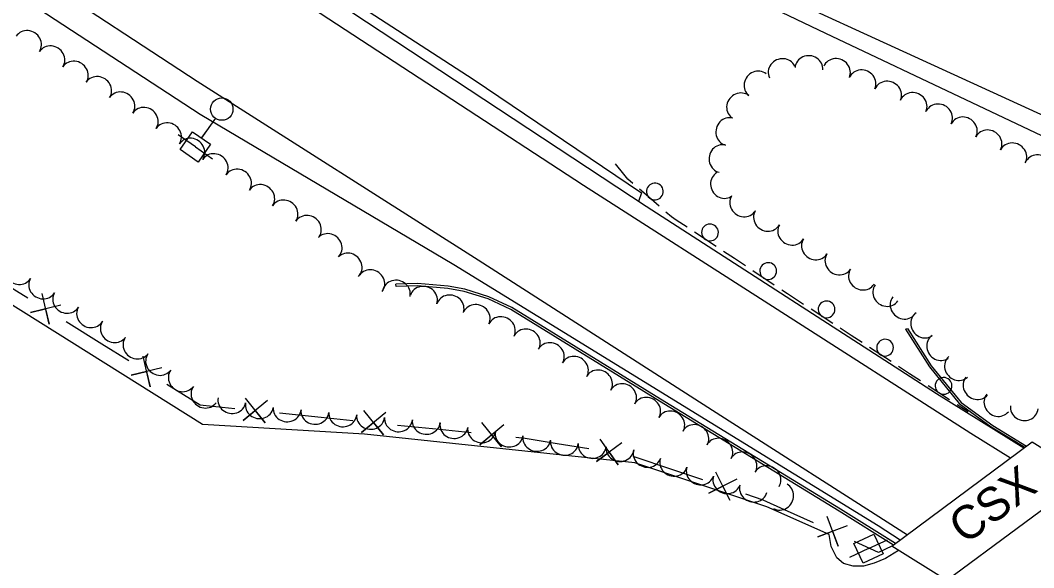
# Model space of a CAD drawing. Extents: x 1746010 to 1754829, y 655801 to 663091.
# Drawn here: x 1751496.6 to 1751859.2, y 659030.7 to 659226.6 of the extents above; entities that cross this region are included whole.
import ezdxf

# ---------------------------------------------------------------- set-up
doc = ezdxf.new("R2010")
doc.units = 0
for name, color, linetype in [('SURVEY - AERIAL SURVEY - Photo Control - Points - Elevations', 7, 'Continuous'), ('SURVEY - AERIAL SURVEY - Photo Control - Points - Locators', 7, 'Continuous'), ('SURVEY - AERIAL SURVEY - Photo Control - Points - Numbers', 7, 'Continuous'), ('SURVEY - CENTERLINE - Existing Roads - Development', 7, 'Continuous'), ('SURVEY - CENTERLINE - Existing Roads Curve Text', 7, 'Continuous'), ('SURVEY - CENTERLINE - Existing Roads Text', 7, 'Continuous'), ('SURVEY - CONTROL - Points - Numbers', 7, 'Continuous')]:
    doc.layers.add(name, color=color, linetype=linetype)

msp = doc.modelspace()

# ---------------------------------------------------------------- linework, layer by layer
at = {"layer": 'SURVEY - AERIAL SURVEY - Photo Control - Points - Elevations'}
for points in [[(1751136.82, 659554.52), (1751217.01, 659499.16), (1751310.15, 659435.49), (1751402.66, 659374.15), (1751479.7, 659322.87), (1751569.69, 659263.28), (1751658.69, 659205.51), (1751718.84, 659164.93), (1751717.79, 659161.8)], [(1751808.51, 659038.41), (1751858.64, 659075.74), (1751878.49, 659063.36), (1751828.11, 659026.2)], [(1751828.11, 659026.2), (1751808.51, 659038.41)]]:
    msp.add_lwpolyline(points, dxfattribs=at)
at = {"layer": 'SURVEY - AERIAL SURVEY - Photo Control - Points - Locators'}
for points in [[(1751850.89, 659069.97), (1751836.71, 659078.71), (1751698.09, 659167.45), (1751556.82, 659259.91), (1751409.51, 659356.6), (1751240.26, 659471.26), (1751108.21, 659560.28), (1750949.44, 659670.61), (1750790.01, 659782.16), (1750639.25, 659888.39), (1750537.27, 659960.87), (1750507.28, 659982.53)], [(1751811.46, 659040.6), (1751803.54, 659045.66), (1751651.7, 659139.14), (1751560.97, 659192.86), (1751430.95, 659277.83), (1751226.31, 659416.5), (1751044.68, 659538.71), (1750870.37, 659656.91), (1750693.9, 659781.14), (1750567.77, 659872.76), (1750445.81, 659959.59)], [(1750464.75, 659959.09), (1750533.91, 659909.95), (1750645.13, 659831.38), (1750753.4, 659754.5), (1750870.59, 659672.13), (1750959.5, 659609.93), (1751081.2, 659527.03), (1751199.52, 659445.74), (1751320.31, 659364.23), (1751443.12, 659281.31), (1751559.93, 659204.83), (1751660.4, 659140.92), (1751744.29, 659087.1), (1751814.04, 659042.53)], [(1751855.66, 659073.53), (1751824.49, 659092.89), (1751720.6, 659159.95), (1751578.18, 659253.97), (1751455.85, 659335.43), (1751347.45, 659406.77), (1751242.7, 659477.43), (1751134.7, 659551.49), (1751142.63, 659562.83), (1751231.24, 659513.59), (1751353.03, 659442.63), (1751480.52, 659374.44), (1751556.22, 659335.73), (1751679.55, 659272.32), (1751784.68, 659222.03), (1751889.47, 659172.35), (1751954.53, 659146.62)], [(1751692.52, 659270.52), (1751888.55, 659180.68), (1751962.99, 659152.25)], [(1751810.9, 659036.92), (1751806.26, 659034), (1751802.13, 659032.39), (1751798.35, 659031.28), (1751794.6, 659031.28), (1751791.12, 659032.21), (1751788.78, 659034.22), (1751786.74, 659038.28), (1751785.99, 659042.56), (1751763.7, 659052.53), (1751716.54, 659068.26), (1751619.81, 659078.53), (1751561.8, 659081.97), (1751438.68, 659159.11), (1751425.89, 659140.29), (1751454.93, 659067.9)]]:
    msp.add_lwpolyline(points, dxfattribs=at)
at = {"layer": 'SURVEY - AERIAL SURVEY - Photo Control - Points - Numbers'}
for points in [[(1751712.57, 659171.6), (1751709.62, 659175.27)], [(1751715.82, 659168.23), (1751714, 659169.82), (1751712.57, 659171.6)], [(1751725.18, 659160.1), (1751720.53, 659164.13), (1751718.23, 659166.13)], [(1751731.31, 659155.14), (1751729.64, 659156.25), (1751727.6, 659158.01)], [(1751735.23, 659152.54), (1751731.31, 659155.14)], [(1751745.56, 659145.69), (1751737.89, 659150.77)], [(1751752.14, 659141.32), (1751748.23, 659143.92)], [(1751756.06, 659138.72), (1751752.14, 659141.32)], [(1751766.39, 659131.86), (1751758.72, 659136.95)], [(1751809.8, 659039.37), (1751790.05, 659051.7), (1751727.21, 659090.04), (1751672.46, 659123.85), (1751664.28, 659127.7), (1751655.64, 659130.37), (1751649.7, 659131.53), (1751638.72, 659132.45), (1751631.04, 659132.2)], [(1751809.1, 659038.85), (1751789.64, 659051), (1751726.84, 659089.32), (1751672.17, 659123.08), (1751664.08, 659126.89), (1751655.5, 659129.54), (1751649.62, 659130.68), (1751638.71, 659131.59), (1751631.07, 659131.33), (1751631.04, 659132.2)], [(1751772.98, 659127.51), (1751771.15, 659128.71), (1751769.06, 659130.09)], [(1751776.92, 659124.94), (1751772.98, 659127.51)], [(1751787.3, 659118.16), (1751779.6, 659123.19)], [(1751793.91, 659113.83), (1751789.98, 659116.41)], [(1751813.33, 659116.08), (1751814.08, 659116.36), (1751822.6, 659102.91), (1751833.23, 659089.88), (1751844.58, 659081.57), (1751856.66, 659074.27)], [(1751813.33, 659116.08), (1751821.9, 659102.58), (1751832.6, 659089.46), (1751844.01, 659081.1), (1751856.04, 659073.81)], [(1751797.85, 659111.27), (1751793.91, 659113.83)], [(1751808.23, 659104.48), (1751800.53, 659109.52)], [(1751814.84, 659100.16), (1751810.91, 659102.73)], [(1751818.78, 659097.59), (1751814.84, 659100.16)], [(1751829.16, 659090.81), (1751821.46, 659095.84)], [(1751835.78, 659086.49), (1751831.84, 659089.06)]]:
    msp.add_lwpolyline(points, dxfattribs=at)
for centre, start, end in [((1751723.69, 659165.34), 342.3037, 342.2897), ((1751743.41, 659150.69), 349.5923, 349.5783), ((1751764.24, 659136.87), 349.5923, 349.5783), ((1751785.11, 659123.15), 350.0073, 349.9933), ((1751806.05, 659109.47), 350.0073, 349.9933), ((1751826.98, 659095.8), 350.0073, 349.9933)]:
    msp.add_arc(centre, 3, start, end, dxfattribs=at)
at = {"layer": 'SURVEY - CENTERLINE - Existing Roads - Development'}
for points in [[(1751499.32, 659127.17), (1751489.63, 659133.18)], [(1751511.17, 659124.65), (1751500.24, 659122.02), (1751505.66, 659123.36), (1751506.95, 659117.85), (1751504.46, 659128.81)], [(1751525.75, 659110.78), (1751513, 659118.69)], [(1751535.44, 659104.77), (1751525.75, 659110.78)], [(1751547.29, 659102.24), (1751536.35, 659099.61), (1751541.78, 659100.95), (1751543.07, 659095.45), (1751540.57, 659106.41)], [(1751562.01, 659088.8), (1751561.02, 659088.9), (1751549.12, 659096.28)], [(1751585.11, 659090.55), (1751576.43, 659083.4), (1751580.72, 659086.98), (1751584.29, 659082.59), (1751577.25, 659091.35)], [(1751573.35, 659087.63), (1751562.01, 659088.8)], [(1751604.29, 659084.46), (1751589.37, 659085.99)], [(1751627.39, 659086.22), (1751618.71, 659079.07), (1751623, 659082.65), (1751626.57, 659078.26), (1751619.53, 659087.02)], [(1751615.63, 659083.3), (1751604.29, 659084.46)], [(1751646.57, 659080.13), (1751631.65, 659081.66)], [(1751669.67, 659081.89), (1751661, 659074.73), (1751665.28, 659078.31), (1751668.85, 659073.93), (1751661.81, 659082.69)], [(1751657.91, 659078.97), (1751646.57, 659080.13)], [(1751688.75, 659075.08), (1751677.25, 659076.99), (1751673.93, 659077.33)], [(1751700, 659073.21), (1751688.75, 659075.08)], [(1751711.91, 659075.39), (1751702.81, 659068.79), (1751707.31, 659072.1), (1751710.6, 659067.5), (1751704.12, 659076.69)], [(1751730.1, 659065.8), (1751715.92, 659070.57), (1751715.88, 659070.58)], [(1751740.9, 659062.17), (1751730.1, 659065.8)], [(1751753.02, 659062.42), (1751742.98, 659057.36), (1751747.95, 659059.9), (1751750.47, 659054.84), (1751745.53, 659064.94)], [(1751770.06, 659051.45), (1751762.38, 659054.94), (1751756.17, 659057.04)], [(1751780.44, 659046.74), (1751770.06, 659051.45)], [(1751792.51, 659045.76), (1751782.02, 659041.74), (1751787.22, 659043.77), (1751789.21, 659038.48), (1751785.32, 659049.03)], [(1751808.51, 659038.41), (1751803.67, 659036.19), (1751795.09, 659040.08)]]:
    msp.add_lwpolyline(points, dxfattribs=at)
at = {"layer": 'SURVEY - CENTERLINE - Existing Roads Curve Text'}
for p, q in [((1751566.49, 659191.62), (1751561.5, 659184.5)), ((1751561.73, 659184.82), (1751563.56, 659187.45)), ((1751559.26, 659181.3), (1751553.12, 659185.6)), ((1751559.26, 659181.3), (1751565.41, 659177)), ((1751800.12, 659037.55), (1751806.9, 659040.75)), ((1751800.12, 659037.55), (1751793.33, 659034.34))]:
    msp.add_line(p, q, dxfattribs=at)
for points in [[(1751553.83, 659180.34), (1751558.3, 659186.73), (1751564.7, 659182.26), (1751560.22, 659175.87)], [(1751794.92, 659039.41), (1751801.98, 659042.74), (1751805.31, 659035.69), (1751798.26, 659032.36)]]:
    msp.add_lwpolyline(points, close=True, dxfattribs=at)
msp.add_circle((1751568.72, 659194.82), 4, dxfattribs=at)
at = {"layer": 'SURVEY - CENTERLINE - Existing Roads Text'}
for centre, major_axis in [((1751499.3, 659218.15), (4.18, -2.74)), ((1751507.66, 659212.67), (4.18, -2.74)), ((1751516.03, 659207.19), (4.18, -2.74)), ((1751769.19, 659208.14), (4.54, 2.09)), ((1751778.81, 659209.26), (4.98, -0.42)), ((1751788.7, 659208.15), (4.57, -2.03)), ((1751760.42, 659203.56), (3.12, 3.91)), ((1751797.84, 659204.1), (4.57, -2.03)), ((1751524.39, 659201.7), (4.17, -2.76)), ((1751806.98, 659200.04), (4.57, -2.03)), ((1751532.72, 659196.18), (4.17, -2.76)), ((1751754.18, 659195.74), (3.12, 3.91)), ((1751816.12, 659195.99), (4.57, -2.03)), ((1751541.06, 659190.65), (4.17, -2.76)), ((1751825.24, 659191.89), (4.43, -2.33)), ((1751549.4, 659185.13), (4.17, -2.76)), ((1751750.22, 659186.79), (1.31, 4.82)), ((1751834.1, 659187.24), (4.43, -2.33)), ((1751842.95, 659182.59), (4.43, -2.33)), ((1751557.74, 659179.61), (4.17, -2.76)), ((1751851.8, 659177.94), (4.43, -2.33)), ((1751566.07, 659174.08), (4.17, -2.76)), ((1751747.77, 659177.13), (1.08, 4.88)), ((1751860.81, 659173.69), (4.53, -2.11)), ((1751574.41, 659168.56), (4.17, -2.76)), ((1751748.38, 659167.82), (-2.53, 4.31)), ((1751582.75, 659163.04), (4.17, -2.76)), ((1751591.08, 659157.51), (4.17, -2.76)), ((1751755.39, 659161.1), (-4.24, 2.65)), ((1751763.92, 659155.91), (-4.33, 2.5)), ((1751599.42, 659151.99), (4.17, -2.76)), ((1751606.91, 659145.43), (3.58, -3.49)), ((1751772.56, 659150.94), (-4.33, 2.5)), ((1751781.06, 659145.7), (-4.21, 2.7)), ((1751614.07, 659138.45), (3.58, -3.49)), ((1751789.47, 659140.3), (-4.21, 2.7)), ((1751495.99, 659136.84), (-4.29, 2.57)), ((1751622.13, 659132.55), (4.03, -2.95)), ((1751797.89, 659134.89), (-4.21, 2.7)), ((1751504.57, 659131.7), (-4.29, 2.57)), ((1751631.19, 659128.87), (4.89, -1.05)), ((1751513.15, 659126.56), (-4.29, 2.57)), ((1751640.94, 659126.69), (4.75, -1.55)), ((1751650.44, 659123.59), (4.75, -1.55)), ((1751806.57, 659129.06), (-4.1, 2.87)), ((1751659.8, 659120.13), (4.5, -2.18)), ((1751812.77, 659124.52), (-3.92, 3.11)), ((1751521.72, 659121.42), (-4.29, 2.57)), ((1751820.06, 659117.84), (-2.89, 4.08)), ((1751530.16, 659116.07), (-4.06, 2.92)), ((1751668.8, 659115.79), (4.5, -2.18)), ((1751677.73, 659111.36), (4.35, -2.47)), ((1751538.27, 659110.22), (-4.06, 2.92)), ((1751686.34, 659106.47), (4.35, -2.47)), ((1751825.77, 659109.77), (-2.89, 4.08)), ((1751546.38, 659104.37), (-4.06, 2.92)), ((1751694.96, 659101.58), (4.35, -2.47)), ((1751832.18, 659102.6), (-3.35, 3.71)), ((1751554.5, 659098.52), (-4.06, 2.92)), ((1751703.57, 659096.69), (4.35, -2.47)), ((1751712.19, 659091.8), (4.35, -2.47)), ((1751838.87, 659095.74), (-3.88, 3.15)), ((1751562.61, 659092.67), (-4.06, 2.92)), ((1751846.32, 659089.7), (-3.88, 3.15)), ((1751572.34, 659090.62), (-4.92, 0.91)), ((1751582.17, 659088.8), (-4.92, 0.91)), ((1751720.8, 659086.91), (4.35, -2.47)), ((1751592.09, 659087.64), (-4.98, 0.45)), ((1751602.05, 659086.74), (-4.98, 0.45)), ((1751612.01, 659085.85), (-4.98, 0.45)), ((1751621.97, 659084.96), (-4.98, 0.45)), ((1751729.42, 659082.02), (4.35, -2.47)), ((1751855.87, 659088.11), (-4.97, 0.57)), ((1751631.93, 659084.07), (-4.98, 0.45)), ((1751641.89, 659083.17), (-4.98, 0.45)), ((1751651.78, 659081.67), (-4.94, 0.76)), ((1751738.03, 659077.14), (4.35, -2.47)), ((1751661.66, 659080.15), (-4.94, 0.76)), ((1751671.54, 659078.63), (-4.94, 0.76)), ((1751681.42, 659077.11), (-4.94, 0.76)), ((1751691.32, 659075.69), (-4.97, 0.56)), ((1751701.26, 659074.57), (-4.97, 0.56)), ((1751746.65, 659072.25), (4.35, -2.47)), ((1751711.2, 659073.45), (-4.97, 0.56)), ((1751720.92, 659071.37), (-4.75, 1.57)), ((1751755.26, 659067.36), (4.35, -2.47)), ((1751730.42, 659068.23), (-4.75, 1.57)), ((1751763.85, 659062.39), (4.27, -2.61)), ((1751739.91, 659065.09), (-4.75, 1.57)), ((1751749.41, 659061.96), (-4.75, 1.57)), ((1751758.95, 659058.95), (-4.81, 1.35)), ((1751768.56, 659056.27), (-2.4, -4.39))]:
    msp.add_ellipse(centre, major_axis=major_axis, ratio=0.940188, start_param=0, end_param=3.141593, dxfattribs=at)

# ---------------------------------------------------------------- texts
at = {"layer": 'SURVEY - CONTROL - Points - Numbers'}
msp.add_text('CSX', height=12, rotation=36.4079, dxfattribs=at).set_placement((1751834.64, 659038.76))

doc.saveas('drawing.dxf')
